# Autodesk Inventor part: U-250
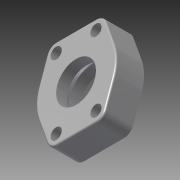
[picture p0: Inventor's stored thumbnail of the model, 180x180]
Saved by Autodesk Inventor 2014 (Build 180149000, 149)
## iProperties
Created: 2011-01
Part Number: U-250
Material: Steel
Document SubType Name: Modeling
Designer: deckm
Density: 7.85 g/cm^3
Description: FLARED FLANGE SAE WITH CLEARANCE HOLES
Mass: 259.498 g
Surface Area: 100.719 cm^2
Volume: 33.0571 cm^3
Appearance: Steel
Author: deckm
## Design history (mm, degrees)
derived "union_cap.ipt"
body "Solid1"
feature "Solid1::union_cap.ipt"
tag "TaggingFeature1"
other parameters: "d1" = 114.046, "d3" = 19.10263, "d25" = 50.8, "FilletTop" = 2, "d27" = 31.75, "d28" = 37 deg, "d29" = 35.56, "d30" = 25.4, "FilletCorners" = 12.573, "FilletEnds" = 54.356, "d8" = 35.56, "d9" = 0, "d12" = 14.2875, "d21" = 50.8, "d24" = 88.9
